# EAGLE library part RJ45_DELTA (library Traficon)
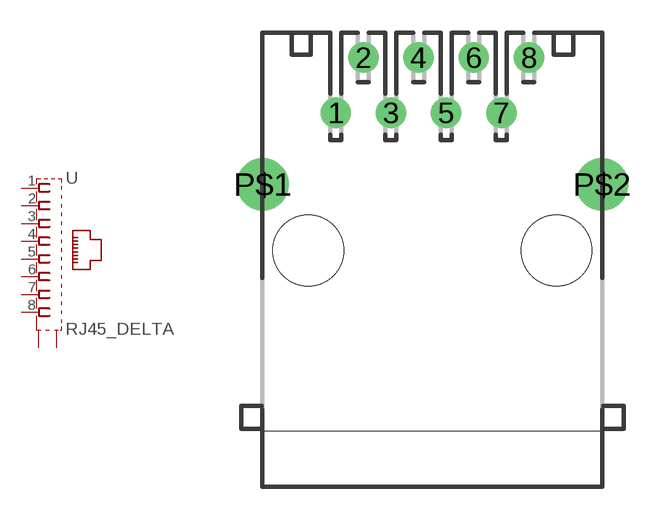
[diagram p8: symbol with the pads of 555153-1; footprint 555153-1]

Designator prefix -

## RJ45_DELTA  [555153-1]
1  1  pas
2  2  pas
3  3  pas
4  4  pas
5  5  pas
6  6  pas
7  7  pas
8  8  pas
P$1  S1  pas
P$2  S2  pas

## Footprint 555153-1 (pad centres in mm)
AMP CONNECTOR
drill 0.889 round: 1 -4.445,6.35; 2 -3.175,8.89; 3 -1.905,6.35; 4 -0.635,8.89; 5 0.635,6.35; 6 1.905,8.89; 7 3.175,6.35; 8 4.445,8.89
drill 1.6 round: P$1 -7.81,3.05; P$2 7.81,3.05
hole 3.251 at -5.715,0
hole 3.251 at 5.715,0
